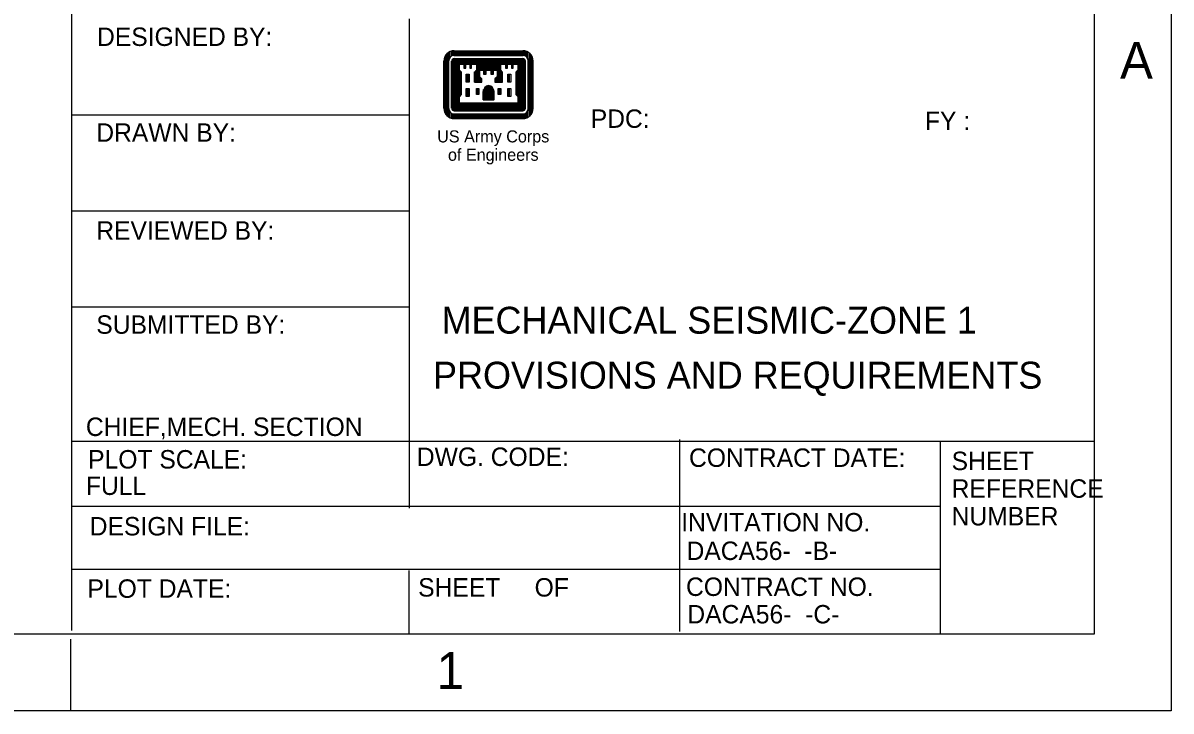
# Model space of a CAD drawing. Extents: x 10040.55 to 10045.84, y 10033.26 to 10035.76.
# Drawn here: x 10043.424 to 10044.047, y 10033.255 to 10033.629 of the extents above; entities that cross this region are included whole.
import ezdxf

# ---------------------------------------------------------------- set-up
doc = ezdxf.new("R2010")
doc.units = 0
for name, color, linetype in [('Level 1', 7, 'Continuous'), ('Level 3', 7, 'Continuous'), ('Level 50', 7, 'Continuous'), ('Level 6', 7, 'Continuous')]:
    doc.layers.add(name, color=color, linetype=linetype)

msp = doc.modelspace()

# ---------------------------------------------------------------- linework, layer by layer
at = {"layer": 'Level 1'}
for p, q in [((10044.04697, 10035.75552), (10044.04697, 10033.25552)), ((10044.0053, 10035.71385), (10044.0053, 10033.29719)), ((10043.45065, 10033.29926), (10043.45065, 10033.72594)), ((10043.63372, 10033.6311), (10043.63372, 10033.36549)), ((10043.45065, 10033.57902), (10043.63372, 10033.57902)), ((10043.45065, 10033.52694), (10043.63372, 10033.52694)), ((10043.45065, 10033.47485), (10043.63372, 10033.47485)), ((10043.45065, 10033.40194), (10044.0053, 10033.40194)), ((10043.78045, 10033.29863), (10043.78045, 10033.40279)), ((10043.92183, 10033.29725), (10043.92183, 10033.40142)), ((10043.45065, 10033.3666), (10043.92183, 10033.3666)), ((10043.92183, 10033.33219), (10043.45065, 10033.33219)), ((10043.63372, 10033.29777), (10043.63372, 10033.33167)), ((10044.0053, 10033.29719), (10040.71364, 10033.29719)), ((10043.45014, 10033.25549), (10043.45014, 10033.29447)), ((10044.04697, 10033.25552), (10040.54697, 10033.25552))]:
    msp.add_line(p, q, dxfattribs=at)
at = {"layer": 'Level 6'}
for p, q in [((10043.65377, 10033.57895), (10043.65377, 10033.61164)), ((10043.65445, 10033.57828), (10043.65445, 10033.61231)), ((10043.65518, 10033.60827), (10043.65518, 10033.61288)), ((10043.65585, 10033.61006), (10043.65585, 10033.61321)), ((10043.65658, 10033.61068), (10043.65658, 10033.61349)), ((10043.65726, 10033.61096), (10043.65726, 10033.61367)), ((10043.65799, 10033.61107), (10043.65799, 10033.61367)), ((10043.65799, 10033.61107), (10043.69551, 10033.61107)), ((10043.65816, 10033.61372), (10043.69534, 10033.61372)), ((10043.65867, 10033.61107), (10043.65867, 10033.61367)), ((10043.6594, 10033.61107), (10043.6594, 10033.61367)), ((10043.66007, 10033.61107), (10043.66007, 10033.61367)), ((10043.6608, 10033.61107), (10043.6608, 10033.61367)), ((10043.66148, 10033.61107), (10043.66148, 10033.61367)), ((10043.66221, 10033.61107), (10043.66221, 10033.61367)), ((10043.66288, 10033.61107), (10043.66288, 10033.61367)), ((10043.6636, 10033.61107), (10043.6636, 10033.61367)), ((10043.66428, 10033.61107), (10043.66428, 10033.61367)), ((10043.66501, 10033.61107), (10043.66501, 10033.61367)), ((10043.66569, 10033.61107), (10043.66569, 10033.61367)), ((10043.66642, 10033.61107), (10043.66642, 10033.61367)), ((10043.66708, 10033.61107), (10043.66708, 10033.61367)), ((10043.66781, 10033.61107), (10043.66781, 10033.61367)), ((10043.66849, 10033.61107), (10043.66849, 10033.61367)), ((10043.66922, 10033.61107), (10043.66922, 10033.61367)), ((10043.6699, 10033.61107), (10043.6699, 10033.61367)), ((10043.67063, 10033.61107), (10043.67063, 10033.61367)), ((10043.67129, 10033.61107), (10043.67129, 10033.61367)), ((10043.67202, 10033.61107), (10043.67202, 10033.61367)), ((10043.6727, 10033.61107), (10043.6727, 10033.61367)), ((10043.67343, 10033.61107), (10043.67343, 10033.61367)), ((10043.6741, 10033.61107), (10043.6741, 10033.61367)), ((10043.67483, 10033.61107), (10043.67483, 10033.61367)), ((10043.67551, 10033.61107), (10043.67551, 10033.61367)), ((10043.67624, 10033.61107), (10043.67624, 10033.61367)), ((10043.67692, 10033.61107), (10043.67692, 10033.61367)), ((10043.67765, 10033.61107), (10043.67765, 10033.61367)), ((10043.67832, 10033.61107), (10043.67832, 10033.61367)), ((10043.67905, 10033.61107), (10043.67905, 10033.61367)), ((10043.67973, 10033.61107), (10043.67973, 10033.61367)), ((10043.68045, 10033.61107), (10043.68045, 10033.61367)), ((10043.68113, 10033.61107), (10043.68113, 10033.61367)), ((10043.68185, 10033.61107), (10043.68185, 10033.61367)), ((10043.68253, 10033.61107), (10043.68253, 10033.61367)), ((10043.68326, 10033.61107), (10043.68326, 10033.61367)), ((10043.68394, 10033.61107), (10043.68394, 10033.61367)), ((10043.68466, 10033.61107), (10043.68466, 10033.61367)), ((10043.68533, 10033.61107), (10043.68533, 10033.61367)), ((10043.68606, 10033.61107), (10043.68606, 10033.61367)), ((10043.68674, 10033.61107), (10043.68674, 10033.61367)), ((10043.68747, 10033.61107), (10043.68747, 10033.61367)), ((10043.68815, 10033.61107), (10043.68815, 10033.61367)), ((10043.68888, 10033.61107), (10043.68888, 10033.61367)), ((10043.68954, 10033.61107), (10043.68954, 10033.61367)), ((10043.69028, 10033.61107), (10043.69028, 10033.61367)), ((10043.69095, 10033.61107), (10043.69095, 10033.61367)), ((10043.69169, 10033.61107), (10043.69169, 10033.61367)), ((10043.69235, 10033.61107), (10043.69235, 10033.61367)), ((10043.69309, 10033.61107), (10043.69309, 10033.61367)), ((10043.69376, 10033.61107), (10043.69376, 10033.61367)), ((10043.6945, 10033.61107), (10043.6945, 10033.61367)), ((10043.69517, 10033.61107), (10043.69517, 10033.61367)), ((10043.69591, 10033.61107), (10043.69591, 10033.61367)), ((10043.69657, 10033.61085), (10043.69657, 10033.6136)), ((10043.69731, 10033.6104), (10043.69731, 10033.61339)), ((10043.69797, 10033.60961), (10043.69797, 10033.61304)), ((10043.69871, 10033.578), (10043.69871, 10033.61259)), ((10043.69944, 10033.57868), (10043.69944, 10033.61192)), ((10043.70011, 10033.57951), (10043.70011, 10033.61107)), ((10043.65254, 10033.58249), (10043.65254, 10033.6081)), ((10043.65305, 10033.58019), (10043.65305, 10033.6104)), ((10043.65518, 10033.58232), (10043.65518, 10033.60827)), ((10043.65675, 10033.58249), (10043.65675, 10033.6081)), ((10043.65726, 10033.58143), (10043.65726, 10033.60918)), ((10043.65799, 10033.58108), (10043.65799, 10033.60951)), ((10043.65816, 10033.60951), (10043.69534, 10033.60951)), ((10043.65867, 10033.58108), (10043.65867, 10033.60951)), ((10043.6594, 10033.58108), (10043.6594, 10033.60951)), ((10043.66007, 10033.58108), (10043.66007, 10033.60951)), ((10043.6608, 10033.58108), (10043.6608, 10033.60951)), ((10043.66097, 10033.60321), (10043.66097, 10033.60636)), ((10043.66097, 10033.60636), (10043.66332, 10033.60636)), ((10043.66097, 10033.60321), (10043.66097, 10033.60636)), ((10043.66097, 10033.60636), (10043.66332, 10033.60636)), ((10043.66148, 10033.60636), (10043.66148, 10033.60951)), ((10043.66221, 10033.60636), (10043.66221, 10033.60951)), ((10043.66288, 10033.60636), (10043.66288, 10033.60951)), ((10043.66332, 10033.60636), (10043.66332, 10033.60422)), ((10043.66332, 10033.60636), (10043.66332, 10033.60422)), ((10043.66332, 10033.60422), (10043.6644, 10033.60422)), ((10043.66332, 10033.60422), (10043.6644, 10033.60422)), ((10043.6636, 10033.60422), (10043.6636, 10033.60951)), ((10043.66428, 10033.60422), (10043.66428, 10033.60951)), ((10043.6644, 10033.60422), (10043.6644, 10033.60636)), ((10043.6644, 10033.60636), (10043.66653, 10033.60636)), ((10043.6644, 10033.60422), (10043.6644, 10033.60636)), ((10043.6644, 10033.60636), (10043.66653, 10033.60636)), ((10043.66501, 10033.60636), (10043.66501, 10033.60951)), ((10043.66569, 10033.60636), (10043.66569, 10033.60951)), ((10043.66642, 10033.60636), (10043.66642, 10033.60951)), ((10043.66653, 10033.60636), (10043.66653, 10033.60422)), ((10043.66653, 10033.60636), (10043.66653, 10033.60422)), ((10043.66653, 10033.60422), (10043.66753, 10033.60422)), ((10043.66653, 10033.60422), (10043.66753, 10033.60422)), ((10043.66708, 10033.60428), (10043.66708, 10033.60951)), ((10043.66753, 10033.60422), (10043.66753, 10033.60636)), ((10043.66753, 10033.60636), (10043.67018, 10033.60636)), ((10043.66753, 10033.60422), (10043.66753, 10033.60636)), ((10043.66753, 10033.60636), (10043.67018, 10033.60636)), ((10043.66781, 10033.60636), (10043.66781, 10033.60951)), ((10043.66849, 10033.60636), (10043.66849, 10033.60951)), ((10043.66922, 10033.60636), (10043.66922, 10033.60951)), ((10043.6699, 10033.60636), (10043.6699, 10033.60951)), ((10043.67018, 10033.60636), (10043.67018, 10033.60321)), ((10043.67018, 10033.60636), (10043.67018, 10033.60321)), ((10043.67063, 10033.59658), (10043.67063, 10033.60951)), ((10043.67129, 10033.59658), (10043.67129, 10033.60951)), ((10043.67202, 10033.60321), (10043.67202, 10033.60951)), ((10043.6727, 10033.60321), (10043.6727, 10033.60951)), ((10043.67343, 10033.60321), (10043.67343, 10033.60951)), ((10043.6741, 10033.60321), (10043.6741, 10033.60951)), ((10043.67483, 10033.60107), (10043.67483, 10033.60951)), ((10043.67551, 10033.60321), (10043.67551, 10033.60951)), ((10043.67624, 10033.60321), (10043.67624, 10033.60951)), ((10043.67692, 10033.60321), (10043.67692, 10033.60951)), ((10043.67765, 10033.60321), (10043.67765, 10033.60951)), ((10043.67832, 10033.60107), (10043.67832, 10033.60951)), ((10043.67905, 10033.60107), (10043.67905, 10033.60951)), ((10043.67973, 10033.60321), (10043.67973, 10033.60951)), ((10043.68045, 10033.60321), (10043.68045, 10033.60951)), ((10043.68045, 10033.60321), (10043.68045, 10033.60951)), ((10043.68113, 10033.60321), (10043.68113, 10033.60951)), ((10043.68185, 10033.59658), (10043.68185, 10033.60951)), ((10043.68253, 10033.59658), (10043.68253, 10033.60951)), ((10043.68326, 10033.59658), (10043.68326, 10033.60951)), ((10043.68338, 10033.60321), (10043.68338, 10033.60636)), ((10043.68338, 10033.60636), (10043.68596, 10033.60636)), ((10043.68394, 10033.60636), (10043.68394, 10033.60951)), ((10043.68466, 10033.60636), (10043.68466, 10033.60951)), ((10043.68533, 10033.60636), (10043.68533, 10033.60951)), ((10043.68596, 10033.60636), (10043.68596, 10033.60422)), ((10043.68596, 10033.60422), (10043.68702, 10033.60422)), ((10043.68606, 10033.60422), (10043.68606, 10033.60951)), ((10043.68674, 10033.60422), (10043.68674, 10033.60951)), ((10043.68702, 10033.60422), (10043.68702, 10033.60636)), ((10043.68702, 10033.60636), (10043.68916, 10033.60636)), ((10043.68747, 10033.60636), (10043.68747, 10033.60951)), ((10043.68821, 10033.60636), (10043.68821, 10033.60951)), ((10043.68888, 10033.60636), (10043.68888, 10033.60951)), ((10043.68916, 10033.60636), (10043.68916, 10033.60422)), ((10043.68916, 10033.60422), (10043.69017, 10033.60422)), ((10043.68954, 10033.60422), (10043.68954, 10033.60951)), ((10043.69017, 10033.60422), (10043.69017, 10033.60636)), ((10043.69017, 10033.60636), (10043.69258, 10033.60636)), ((10043.69028, 10033.60636), (10043.69028, 10033.60951)), ((10043.69095, 10033.60636), (10043.69095, 10033.60951)), ((10043.69169, 10033.60636), (10043.69169, 10033.60951)), ((10043.69235, 10033.60636), (10043.69235, 10033.60951)), ((10043.69258, 10033.60636), (10043.69258, 10033.60321)), ((10043.69309, 10033.58108), (10043.69309, 10033.60951)), ((10043.69376, 10033.58108), (10043.69376, 10033.60951)), ((10043.6945, 10033.58108), (10043.6945, 10033.60951)), ((10043.69517, 10033.58108), (10043.69517, 10033.60951)), ((10043.69591, 10033.5812), (10043.69591, 10033.6094)), ((10043.69657, 10033.58181), (10043.69657, 10033.60878)), ((10043.69675, 10033.58249), (10043.69675, 10033.6081)), ((10043.69831, 10033.58232), (10043.69831, 10033.60827)), ((10043.70084, 10033.58136), (10043.70084, 10033.60923)), ((10043.70096, 10033.58249), (10043.70096, 10033.6081)), ((10043.66204, 10033.60215), (10043.66097, 10033.60321)), ((10043.66204, 10033.60215), (10043.66097, 10033.60321)), ((10043.66153, 10033.5894), (10043.66153, 10033.60265)), ((10043.66204, 10033.59002), (10043.66204, 10033.60215)), ((10043.66204, 10033.59002), (10043.66204, 10033.60215)), ((10043.66468, 10033.59658), (10043.66468, 10033.60107)), ((10043.66468, 10033.60107), (10043.66625, 10033.60107)), ((10043.66501, 10033.59658), (10043.66501, 10033.60107)), ((10043.66569, 10033.59658), (10043.66569, 10033.60107)), ((10043.66625, 10033.60107), (10043.66625, 10033.59658)), ((10043.67018, 10033.60321), (10043.6691, 10033.60215)), ((10043.67018, 10033.60321), (10043.6691, 10033.60215)), ((10043.6691, 10033.60215), (10043.6691, 10033.59658)), ((10043.6691, 10033.60215), (10043.6691, 10033.59658)), ((10043.66922, 10033.59658), (10043.66922, 10033.60225)), ((10043.66995, 10033.59658), (10043.66995, 10033.60299)), ((10043.67202, 10033.59951), (10043.67202, 10033.60321)), ((10043.67202, 10033.60321), (10043.6741, 10033.60321)), ((10043.67202, 10033.59658), (10043.67202, 10033.59951)), ((10043.67309, 10033.59844), (10043.67202, 10033.59951)), ((10043.6727, 10033.59658), (10043.6727, 10033.59883)), ((10043.67309, 10033.59658), (10043.67309, 10033.59844)), ((10043.6741, 10033.60321), (10043.6741, 10033.60107)), ((10043.6741, 10033.60107), (10043.67546, 10033.60107)), ((10043.67546, 10033.60107), (10043.67546, 10033.60321)), ((10043.67546, 10033.60321), (10043.67809, 10033.60321)), ((10043.67809, 10033.60321), (10043.67809, 10033.60107)), ((10043.67809, 10033.60107), (10043.6794, 10033.60107)), ((10043.6794, 10033.60107), (10043.6794, 10033.60321)), ((10043.6794, 10033.60321), (10043.68152, 10033.60321)), ((10043.68152, 10033.59951), (10043.68017, 10033.59844)), ((10043.68017, 10033.59844), (10043.68017, 10033.59658)), ((10043.68045, 10033.59658), (10043.68045, 10033.59867)), ((10043.68119, 10033.59658), (10043.68119, 10033.59923)), ((10043.68152, 10033.60321), (10043.68152, 10033.59951)), ((10043.68438, 10033.60215), (10043.68338, 10033.60321)), ((10043.684, 10033.59658), (10043.684, 10033.60253)), ((10043.68438, 10033.59658), (10043.68438, 10033.60215)), ((10043.6873, 10033.59658), (10043.6873, 10033.60107)), ((10043.6873, 10033.60107), (10043.68888, 10033.60107)), ((10043.68747, 10033.59658), (10043.68747, 10033.60107)), ((10043.68815, 10033.59658), (10043.68815, 10033.60107)), ((10043.68888, 10033.60107), (10043.68888, 10033.59658)), ((10043.69258, 10033.60321), (10043.69151, 10033.60215)), ((10043.69151, 10033.60215), (10043.69151, 10033.59002)), ((10043.69169, 10033.58985), (10043.69169, 10033.60231)), ((10043.69235, 10033.58918), (10043.69235, 10033.60299)), ((10043.66625, 10033.59658), (10043.66468, 10033.59658)), ((10043.66468, 10033.58895), (10043.66468, 10033.59316)), ((10043.66468, 10033.59316), (10043.66625, 10033.59316)), ((10043.66501, 10033.58895), (10043.66501, 10033.59316)), ((10043.66569, 10033.58895), (10043.66569, 10033.59316)), ((10043.66625, 10033.59316), (10043.66625, 10033.58895)), ((10043.6691, 10033.59658), (10043.67309, 10033.59658)), ((10043.6691, 10033.59658), (10043.67309, 10033.59658)), ((10043.67018, 10033.59002), (10043.67018, 10033.59316)), ((10043.67018, 10033.59316), (10043.67152, 10033.59316)), ((10043.67063, 10033.59002), (10043.67063, 10033.59316)), ((10043.67129, 10033.59002), (10043.67129, 10033.59316)), ((10043.67152, 10033.59316), (10043.67152, 10033.59002)), ((10043.6741, 10033.58715), (10043.6741, 10033.59271)), ((10043.67483, 10033.58715), (10043.67483, 10033.59378)), ((10043.67551, 10033.58715), (10043.67551, 10033.59434)), ((10043.67624, 10033.58715), (10043.67624, 10033.59468)), ((10043.67692, 10033.58715), (10043.67692, 10033.59479)), ((10043.67765, 10033.58715), (10043.67765, 10033.59456)), ((10043.67832, 10033.58715), (10043.67832, 10033.59418)), ((10043.67905, 10033.58715), (10043.67905, 10033.5935)), ((10043.68017, 10033.59658), (10043.68438, 10033.59658)), ((10043.68203, 10033.59002), (10043.68203, 10033.59316)), ((10043.68203, 10033.59316), (10043.68338, 10033.59316)), ((10043.68253, 10033.59002), (10043.68253, 10033.59316)), ((10043.68326, 10033.59002), (10043.68326, 10033.59316)), ((10043.68338, 10033.59316), (10043.68338, 10033.59002)), ((10043.68888, 10033.59658), (10043.6873, 10033.59658)), ((10043.6873, 10033.58895), (10043.6873, 10033.59316)), ((10043.6873, 10033.59316), (10043.68888, 10033.59316)), ((10043.68747, 10033.58895), (10043.68747, 10033.59316)), ((10043.68815, 10033.58895), (10043.68815, 10033.59316)), ((10043.68888, 10033.59316), (10043.68888, 10033.58895)), ((10043.66097, 10033.58873), (10043.66204, 10033.59002)), ((10043.66097, 10033.58873), (10043.66204, 10033.59002)), ((10043.66097, 10033.58529), (10043.66097, 10033.58873)), ((10043.66097, 10033.58529), (10043.66097, 10033.58873)), ((10043.66625, 10033.58895), (10043.66468, 10033.58895)), ((10043.67152, 10033.59002), (10043.67018, 10033.59002)), ((10043.67388, 10033.58715), (10043.67388, 10033.59159)), ((10043.67973, 10033.58715), (10043.67388, 10033.58715)), ((10043.67388, 10033.58715), (10043.67968, 10033.58715)), ((10043.67973, 10033.58715), (10043.67973, 10033.59159)), ((10043.68338, 10033.59002), (10043.68203, 10033.59002)), ((10043.68888, 10033.58895), (10043.6873, 10033.58895)), ((10043.69151, 10033.59002), (10043.69258, 10033.58895)), ((10043.69258, 10033.58895), (10043.69258, 10033.58529)), ((10043.65518, 10033.57772), (10043.65518, 10033.58232)), ((10043.65585, 10033.57739), (10043.65585, 10033.58052)), ((10043.65658, 10033.5771), (10043.65658, 10033.57991)), ((10043.65726, 10033.57693), (10043.65726, 10033.57963)), ((10043.65799, 10033.57951), (10043.69551, 10033.57951)), ((10043.65799, 10033.57693), (10043.65799, 10033.57951)), ((10043.65816, 10033.58108), (10043.69534, 10033.58108)), ((10043.65867, 10033.57693), (10043.65867, 10033.57951)), ((10043.6594, 10033.57693), (10043.6594, 10033.57951)), ((10043.66007, 10033.57693), (10043.66007, 10033.57951)), ((10043.6608, 10033.57693), (10043.6608, 10033.57951)), ((10043.69258, 10033.58529), (10043.66097, 10033.58529)), ((10043.66148, 10033.58108), (10043.66148, 10033.58529)), ((10043.66148, 10033.57693), (10043.66148, 10033.57951)), ((10043.66221, 10033.58108), (10043.66221, 10033.58529)), ((10043.66221, 10033.57693), (10043.66221, 10033.57951)), ((10043.66288, 10033.58108), (10043.66288, 10033.58529)), ((10043.66288, 10033.57693), (10043.66288, 10033.57951)), ((10043.6636, 10033.58108), (10043.6636, 10033.58529)), ((10043.6636, 10033.57693), (10043.6636, 10033.57951)), ((10043.66428, 10033.58108), (10043.66428, 10033.58529)), ((10043.66428, 10033.57693), (10043.66428, 10033.57951)), ((10043.66501, 10033.58108), (10043.66501, 10033.58529)), ((10043.66501, 10033.57693), (10043.66501, 10033.57951)), ((10043.66569, 10033.58108), (10043.66569, 10033.58529)), ((10043.66569, 10033.57693), (10043.66569, 10033.57951)), ((10043.66642, 10033.58108), (10043.66642, 10033.58529)), ((10043.66642, 10033.57693), (10043.66642, 10033.57951)), ((10043.66708, 10033.58108), (10043.66708, 10033.58529)), ((10043.66708, 10033.57693), (10043.66708, 10033.57951)), ((10043.66781, 10033.58108), (10043.66781, 10033.58529)), ((10043.66781, 10033.57693), (10043.66781, 10033.57951)), ((10043.66849, 10033.58108), (10043.66849, 10033.58529)), ((10043.66849, 10033.57693), (10043.66849, 10033.57951)), ((10043.66922, 10033.58108), (10043.66922, 10033.58529)), ((10043.66922, 10033.57693), (10043.66922, 10033.57951)), ((10043.6699, 10033.58108), (10043.6699, 10033.58529)), ((10043.6699, 10033.57693), (10043.6699, 10033.57951)), ((10043.67063, 10033.58108), (10043.67063, 10033.58529)), ((10043.67063, 10033.57693), (10043.67063, 10033.57951)), ((10043.67129, 10033.58108), (10043.67129, 10033.58529)), ((10043.67129, 10033.57693), (10043.67129, 10033.57951)), ((10043.67202, 10033.58108), (10043.67202, 10033.58529)), ((10043.67202, 10033.57693), (10043.67202, 10033.57951)), ((10043.6727, 10033.58108), (10043.6727, 10033.58529)), ((10043.6727, 10033.57693), (10043.6727, 10033.57951)), ((10043.67343, 10033.58108), (10043.67343, 10033.58529)), ((10043.67343, 10033.57693), (10043.67343, 10033.57951)), ((10043.6741, 10033.58108), (10043.6741, 10033.58529)), ((10043.6741, 10033.57693), (10043.6741, 10033.57951)), ((10043.67483, 10033.58108), (10043.67483, 10033.58529)), ((10043.67483, 10033.57693), (10043.67483, 10033.57951)), ((10043.67551, 10033.58108), (10043.67551, 10033.58529)), ((10043.67551, 10033.57693), (10043.67551, 10033.57951)), ((10043.67624, 10033.58108), (10043.67624, 10033.58529)), ((10043.67624, 10033.57693), (10043.67624, 10033.57951)), ((10043.67692, 10033.58108), (10043.67692, 10033.58529)), ((10043.67692, 10033.57693), (10043.67692, 10033.57951)), ((10043.67765, 10033.58108), (10043.67765, 10033.58529)), ((10043.67765, 10033.57693), (10043.67765, 10033.57951)), ((10043.67832, 10033.58108), (10043.67832, 10033.58529)), ((10043.67832, 10033.57693), (10043.67832, 10033.57951)), ((10043.67905, 10033.58108), (10043.67905, 10033.58529)), ((10043.67905, 10033.57693), (10043.67905, 10033.57951)), ((10043.67973, 10033.58108), (10043.67973, 10033.58529)), ((10043.67973, 10033.57693), (10043.67973, 10033.57951)), ((10043.68045, 10033.58108), (10043.68045, 10033.58529)), ((10043.68045, 10033.57693), (10043.68045, 10033.57951)), ((10043.68113, 10033.58108), (10043.68113, 10033.58529)), ((10043.68113, 10033.57693), (10043.68113, 10033.57951)), ((10043.68185, 10033.58108), (10043.68185, 10033.58529)), ((10043.68185, 10033.57693), (10043.68185, 10033.57951)), ((10043.68253, 10033.58108), (10043.68253, 10033.58529)), ((10043.68253, 10033.57693), (10043.68253, 10033.57951)), ((10043.68326, 10033.58108), (10043.68326, 10033.58529)), ((10043.68326, 10033.57693), (10043.68326, 10033.57951)), ((10043.68394, 10033.58108), (10043.68394, 10033.58529)), ((10043.68394, 10033.57693), (10043.68394, 10033.57951)), ((10043.68466, 10033.58108), (10043.68466, 10033.58529)), ((10043.68466, 10033.57693), (10043.68466, 10033.57951)), ((10043.68533, 10033.58108), (10043.68533, 10033.58529)), ((10043.68533, 10033.57693), (10043.68533, 10033.57951)), ((10043.68606, 10033.58108), (10043.68606, 10033.58529)), ((10043.68606, 10033.57693), (10043.68606, 10033.57951)), ((10043.68674, 10033.58108), (10043.68674, 10033.58529)), ((10043.68674, 10033.57693), (10043.68674, 10033.57951)), ((10043.68747, 10033.58108), (10043.68747, 10033.58529)), ((10043.68747, 10033.57693), (10043.68747, 10033.57951)), ((10043.68815, 10033.58108), (10043.68815, 10033.58529)), ((10043.68815, 10033.57693), (10043.68815, 10033.57951)), ((10043.68888, 10033.58108), (10043.68888, 10033.58529)), ((10043.68888, 10033.57693), (10043.68888, 10033.57951)), ((10043.68954, 10033.58108), (10043.68954, 10033.58529)), ((10043.68954, 10033.57693), (10043.68954, 10033.57951)), ((10043.69028, 10033.58108), (10043.69028, 10033.58529)), ((10043.69028, 10033.57693), (10043.69028, 10033.57951)), ((10043.69095, 10033.58108), (10043.69095, 10033.58529)), ((10043.69095, 10033.57693), (10043.69095, 10033.57951)), ((10043.69169, 10033.58108), (10043.69169, 10033.58529)), ((10043.69169, 10033.57693), (10043.69169, 10033.57951)), ((10043.69235, 10033.58108), (10043.69235, 10033.58529)), ((10043.69235, 10033.57693), (10043.69235, 10033.57951)), ((10043.69309, 10033.57693), (10043.69309, 10033.57951)), ((10043.69376, 10033.57693), (10043.69376, 10033.57951)), ((10043.6945, 10033.57693), (10043.6945, 10033.57951)), ((10043.69517, 10033.57693), (10043.69517, 10033.57951)), ((10043.69591, 10033.57693), (10043.69591, 10033.57951)), ((10043.69657, 10033.57699), (10043.69657, 10033.57974)), ((10043.69731, 10033.57721), (10043.69731, 10033.58019)), ((10043.69797, 10033.57755), (10043.69797, 10033.58097)), ((10043.65816, 10033.57688), (10043.69534, 10033.57688))]:
    msp.add_line(p, q, dxfattribs=at)
for centre, radius, start, end in [((10043.65816, 10033.6081), 0.00562, 90, 180), ((10043.65799, 10033.60827), 0.00281, 90, 180), ((10043.69534, 10033.6081), 0.00562, 0, 90), ((10043.69551, 10033.60827), 0.00281, 0, 90), ((10043.65816, 10033.6081), 0.0014, 90, 180), ((10043.69534, 10033.6081), 0.0014, 0, 90), ((10043.67726, 10033.59142), 0.0034, 97.72175, 177.14315), ((10043.67635, 10033.59142), 0.0034, 2.85685, 82.27825), ((10043.65816, 10033.58249), 0.00562, 180, 270), ((10043.65799, 10033.58232), 0.00281, 180, 270), ((10043.65816, 10033.58249), 0.0014, 180, 270), ((10043.69534, 10033.58249), 0.00562, 270, 0), ((10043.69534, 10033.58249), 0.0014, 270, 0), ((10043.69551, 10033.58232), 0.00281, 270, 0)]:
    msp.add_arc(centre, radius, start, end, dxfattribs=at)

# ---------------------------------------------------------------- texts
at = {"layer": 'Level 1'}
for s, height, p in [('DESIGNED BY:', 0.01, (10043.46438, 10033.61631)), ('A', 0.02, (10044.0193, 10033.59852)), ('PDC:', 0.009984, (10043.73222, 10033.57188)), ('FY :', 0.009984, (10043.91351, 10033.57072)), ('DRAWN BY:', 0.01, (10043.46398, 10033.56433)), ('REVIEWED BY:', 0.01, (10043.46398, 10033.5112)), ('SUBMITTED BY:', 0.01, (10043.46398, 10033.46016)), ('PLOT SCALE:', 0.01, (10043.45956, 10033.38707)), ('DWG. CODE:', 0.01, (10043.63784, 10033.38845)), ('CONTRACT DATE:', 0.01, (10043.78551, 10033.38794)), ('SHEET', 0.01, (10043.92794, 10033.3862)), ('REFERENCE', 0.01, (10043.92794, 10033.3712)), ('INVITATION NO.', 0.01, (10043.78128, 10033.35294)), ('NUMBER', 0.01, (10043.92794, 10033.3562)), ('DESIGN FILE:', 0.01, (10043.46042, 10033.35075)), ('DACA56-  -B-    ', 0.01, (10043.78416, 10033.33744)), ('PLOT DATE:', 0.01, (10043.4592, 10033.31692)), ('SHEET     OF', 0.01, (10043.63859, 10033.31759)), ('CONTRACT NO.', 0.01, (10043.78389, 10033.31793)), ('DACA56-  -C-    ', 0.01, (10043.78458, 10033.30302)), ('1', 0.02, (10043.64864, 10033.26752))]:
    msp.add_text(s, height=height, dxfattribs=at).set_placement(p)
at = {"layer": 'Level 3'}
for s, height, p in [('   MECHANICAL SEISMIC-ZONE 1   ', 0.0145816, (10043.63504, 10033.46023)), ('  PROVISIONS AND REQUIREMENTS  ', 0.0145833, (10043.63583, 10033.43042)), ('CHIEF,MECH. SECTION', 0.01, (10043.45835, 10033.40471)), ('FULL              ', 0.0100011, (10043.45835, 10033.37273))]:
    msp.add_text(s, height=height, dxfattribs=at).set_placement(p)
at = {"layer": 'Level 50'}
for s, p in [('US Army Corps', (10043.6489, 10033.56397)), ('of Engineers', (10043.65475, 10033.55401))]:
    msp.add_text(s, height=0.0065473, dxfattribs=at).set_placement(p)

doc.saveas('drawing.dxf')
